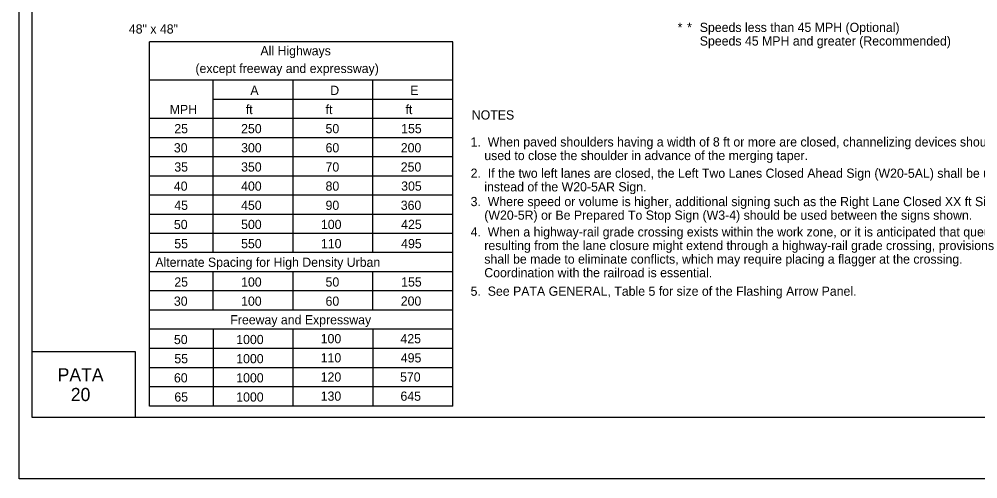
# Model space of a CAD drawing. Extents: x -14145 to -13662, y 30244 to 30661.
# Drawn here: x -13926.17 to -13904.31, y 30370.81 to 30381.29 of the extents above; entities that cross this region are included whole.
import ezdxf

# ---------------------------------------------------------------- set-up
doc = ezdxf.new("R2010")
doc.units = 0
for name, color, linetype in [('1', 7, 'Continuous'), ('10', 7, 'Continuous'), ('2', 7, 'Continuous'), ('3', 7, 'Continuous'), ('4', 7, 'Continuous'), ('61', 7, 'Continuous')]:
    doc.layers.add(name, color=color, linetype=linetype)

msp = doc.modelspace()

# ---------------------------------------------------------------- linework, layer by layer
at = {"layer": '1'}
for p, q in [((-13916.281, 30380.771), (-13923.202, 30380.771)), ((-13923.202, 30372.467), (-13923.202, 30380.771)), ((-13916.281, 30372.467), (-13916.281, 30380.771)), ((-13916.281, 30379.897), (-13923.203, 30379.897)), ((-13921.745, 30375.964), (-13921.745, 30379.897)), ((-13919.924, 30375.964), (-13919.924, 30379.897)), ((-13918.103, 30375.964), (-13918.103, 30379.897)), ((-13916.281, 30379.46), (-13921.745, 30379.46)), ((-13916.281, 30379.023), (-13923.203, 30379.023)), ((-13916.281, 30378.586), (-13923.203, 30378.586)), ((-13916.281, 30378.149), (-13923.203, 30378.149)), ((-13916.281, 30377.712), (-13923.203, 30377.712)), ((-13916.281, 30377.275), (-13923.203, 30377.275)), ((-13916.281, 30376.838), (-13923.203, 30376.838)), ((-13916.281, 30376.401), (-13923.203, 30376.401)), ((-13916.281, 30375.964), (-13923.203, 30375.964)), ((-13916.282, 30375.527), (-13923.203, 30375.527)), ((-13916.281, 30375.527), (-13923.203, 30375.527)), ((-13921.745, 30374.653), (-13921.745, 30375.527)), ((-13919.924, 30374.653), (-13919.924, 30375.527)), ((-13918.103, 30374.653), (-13918.103, 30375.527)), ((-13916.281, 30375.09), (-13923.203, 30375.09)), ((-13916.281, 30374.653), (-13923.202, 30374.653)), ((-13916.281, 30374.216), (-13923.202, 30374.216)), ((-13921.743, 30372.467), (-13921.743, 30374.216)), ((-13919.923, 30372.467), (-13919.923, 30374.216)), ((-13918.101, 30372.467), (-13918.101, 30374.216)), ((-13916.281, 30373.778), (-13923.202, 30373.778)), ((-13916.281, 30373.341), (-13923.202, 30373.341)), ((-13916.281, 30372.904), (-13923.202, 30372.904)), ((-13916.281, 30372.467), (-13923.202, 30372.467))]:
    msp.add_line(p, q, dxfattribs=at)
at = {"layer": '10'}
for p, q in [((-13925.874, 30372.207), (-13925.874, 30394.777)), ((-13925.874, 30373.707), (-13923.524, 30373.707)), ((-13923.524, 30373.707), (-13923.524, 30372.207)), ((-13894.422, 30372.207), (-13925.874, 30372.207))]:
    msp.add_line(p, q, dxfattribs=at)
at = {"layer": '61'}
msp.add_lwpolyline([(-13926.174, 30396.307), (-13893.174, 30396.307), (-13893.174, 30370.807), (-13926.174, 30370.807)], close=True, dxfattribs=at)

# ---------------------------------------------------------------- texts
at = {"layer": '2'}
for s, p in [('48" x 48"', (-13923.672, 30380.96)), ('*', (-13911.154, 30380.997)), ('*', (-13910.938, 30380.997)), ('Speeds less than 45 MPH (Optional)', (-13910.649, 30380.997)), ('Speeds 45 MPH and greater (Recommended)', (-13910.649, 30380.687)), ('A', (-13920.9, 30379.561)), ('D', (-13919.077, 30379.561)), ('E', (-13917.253, 30379.561)), ('MPH', (-13922.74, 30379.124)), ('ft', (-13921.005, 30379.124)), ('ft', (-13919.184, 30379.124)), ('ft', (-13917.362, 30379.124)), ('NOTES', (-13915.849, 30379)), ('25', (-13922.635, 30378.687)), ('250', (-13921.111, 30378.688)), ('50', (-13919.185, 30378.688)), ('155', (-13917.46, 30378.688)), ('1.  When paved shoulders having a width of 8 ft or more are closed, channelizing devices should be', (-13915.876, 30378.385)), ('30', (-13922.645, 30378.25)), ('300', (-13921.111, 30378.251)), ('60', (-13919.185, 30378.251)), ('200', (-13917.469, 30378.251)), ('    used to close the shoulder in advance of the merging taper.', (-13915.876, 30378.075)), ('35', (-13922.635, 30377.813)), ('350', (-13921.111, 30377.814)), ('70', (-13919.185, 30377.814)), ('250', (-13917.469, 30377.814)), ('2.  If the two left lanes are closed, the Left Two Lanes Closed Ahead Sign (W20-5AL) shall be used', (-13915.876, 30377.671)), ('40', (-13922.645, 30377.376)), ('400', (-13921.111, 30377.377)), ('80', (-13919.185, 30377.377)), ('305', (-13917.46, 30377.377)), ('    instead of the W20-5AR Sign.', (-13915.876, 30377.361)), ('3.  Where speed or volume is higher, additional signing such as the Right Lane Closed XX ft Sign ', (-13915.876, 30377.025)), ('45', (-13922.635, 30376.939)), ('450', (-13921.111, 30376.94)), ('90', (-13919.185, 30376.94)), ('360', (-13917.469, 30376.94)), ('    (W20-5R) or Be Prepared To Stop Sign (W3-4) should be used between the signs shown.', (-13915.876, 30376.715)), ('50', (-13922.644, 30376.502)), ('500', (-13921.111, 30376.503)), ('100', (-13919.29, 30376.503)), ('425', (-13917.46, 30376.503)), ('4.  When a highway-rail grade crossing exists within the work zone, or it is anticipated that queues', (-13915.876, 30376.333)), ('55', (-13922.635, 30376.064)), ('550', (-13921.111, 30376.066)), ('110', (-13919.29, 30376.066)), ('495', (-13917.46, 30376.066)), ('    resulting from the lane closure might extend through a highway-rail grade crossing, provisions', (-13915.876, 30376.023)), ('    shall be made to eliminate conflicts, which may require placing a flagger at the crossing.', (-13915.876, 30375.713)), ('    Coordination with the railroad is essential.', (-13915.876, 30375.403)), ('25', (-13922.635, 30375.19)), ('100', (-13921.111, 30375.19)), ('50', (-13919.185, 30375.19)), ('155', (-13917.46, 30375.192)), ('5.  See PATA GENERAL, Table 5 for size of the Flashing Arrow Panel.', (-13915.876, 30374.981)), ('30', (-13922.644, 30374.753)), ('100', (-13921.111, 30374.753)), ('60', (-13919.185, 30374.753)), ('200', (-13917.469, 30374.755)), ('50', (-13922.643, 30373.879)), ('1000', (-13921.222, 30373.879)), ('100', (-13919.296, 30373.898)), ('425', (-13917.476, 30373.898)), ('55', (-13922.634, 30373.442)), ('1000', (-13921.222, 30373.442)), ('110', (-13919.296, 30373.461)), ('495', (-13917.468, 30373.461)), ('60', (-13922.643, 30373.005)), ('1000', (-13921.222, 30373.005)), ('120', (-13919.296, 30373.024)), ('570', (-13917.485, 30373.024)), ('65', (-13922.634, 30372.568)), ('1000', (-13921.222, 30372.568)), ('130', (-13919.296, 30372.587)), ('645', (-13917.476, 30372.587))]:
    msp.add_text(s, height=0.21, dxfattribs=at).set_placement(p)
at = {"layer": '3'}
for s, height, p in [('All Highways', 0.20979, (-13920.67, 30380.464)), ('(except freeway and expressway)', 0.21, (-13922.153, 30380.061)), ('Alternate Spacing for High Density Urban', 0.20979, (-13923.068, 30375.641)), ('Freeway and Expressway', 0.20979, (-13921.357, 30374.329))]:
    msp.add_text(s, height=height, dxfattribs=at).set_placement(p)
at = {"layer": '4'}
for s, p in [('PATA', (-13925.296, 30373.03)), ('20', (-13924.996, 30372.58))]:
    msp.add_text(s, height=0.3, dxfattribs=at).set_placement(p)

doc.saveas('drawing.dxf')
